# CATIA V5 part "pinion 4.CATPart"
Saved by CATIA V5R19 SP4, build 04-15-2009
Part number: pinion 4
Bounding box of the stored display mesh (mm): x 0 to 22.15, y -45.856 to 45.856, z -45.66 to 45.66
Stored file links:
  G:\EU_thinkMotion\CFAO_2010\MMS_groupe1\MMS_groupe1\A reprendre\OK\rdeneffle\pinion 4.CATPart
  G:\EU_thinkMotion\CFAO_2010\MMS_groupe1\MMS_groupe1\A reprendre\OK\rdeneffle\pinion 2.CATPart
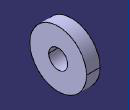
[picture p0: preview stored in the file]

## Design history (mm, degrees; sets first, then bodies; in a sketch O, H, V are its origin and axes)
Parameters
  `rayon interieur.1` = 15.505 mm
  `rayon extérieur.1` = 45.856 mm
Body1 (main body)
Body2
  Sketch1 on yz-plane, origin (0, 0, 0), H (0, 1, 0), V (0, 0, 1)
    circle A1 centre (0, 0) radius 15.505
    circle A2 centre (0, 0) radius 45.856
    radius A2 = 45.856 {= `rayon extérieur.1`}
    radius A1 = 15.505 {= `rayon interieur.1`}
  Pad1: profile Sketch1, direction (1, 0, 0), length 22.15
